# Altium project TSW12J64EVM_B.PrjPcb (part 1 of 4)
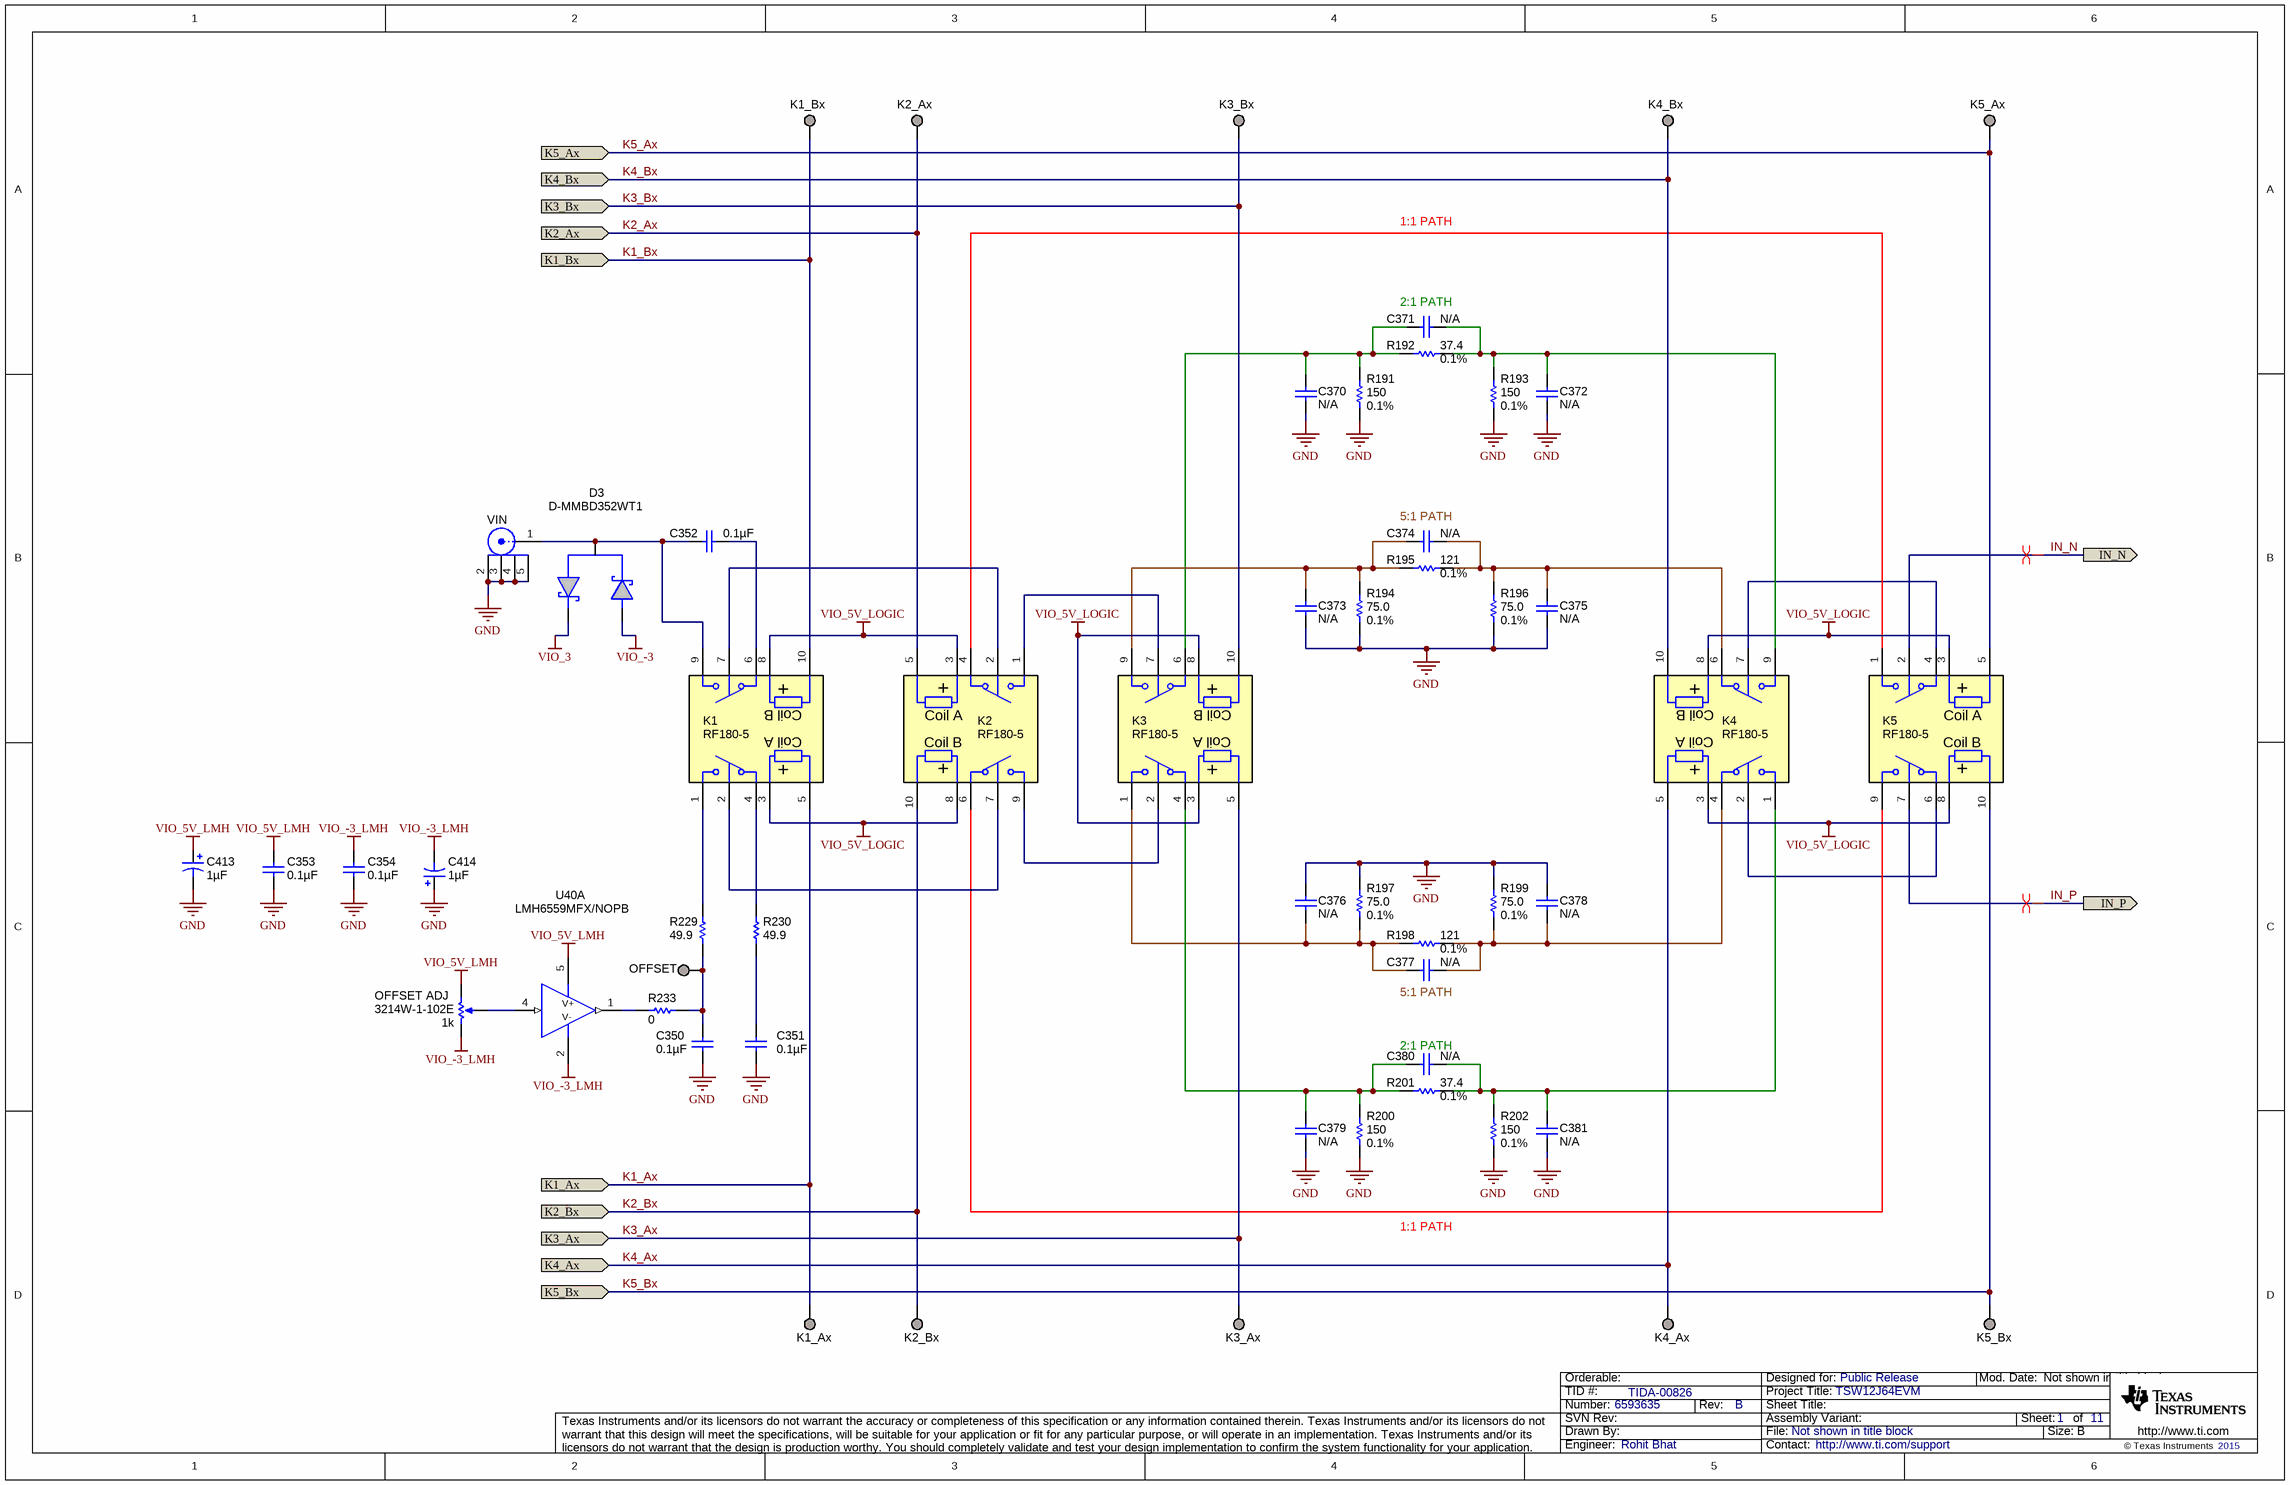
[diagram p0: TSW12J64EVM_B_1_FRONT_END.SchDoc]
TID: TIDA-00826; TechSupport: http://www.ti.com/support; SCH_Rev: B; PRJ_Title: TSW12J64EVM; PRJ_Number: 6593635; PRJ_Engineer: Rohit Bhat; PRJ_Customer: Public Release; PCB_Rev: B; PCB_Layout: Bob Holtz; CopyrightYear: 2015
10 sheets, 892 parts. Net scope: flat (ports and power ports of the same name join across sheets).
Board file: TSW12J64EVM_B.PcbDoc
Sheets:
  TSW12J64EVM_B_1_FRONT_END.SchDoc
  TSW12J64EVM_B_2_RELAY_CONTROL.SchDoc
  TSW12J64EVM_B_3_ANALOG_IN.SchDoc
  TSW12J64EVM_B_4_ADC_IO.SchDoc
  TSW12J64EVM_B_5_FMC.SchDoc
  TSW12J64EVM_B_6_TRF3765.SchDoc
  TSW12J64EVM_B_8_Power.SchDoc
  TSW12J64EVM_B_9_Power.SchDoc
  TSW12J64EVM_B_10_InterfaceControl.SchDoc
  TSW12J64EVM_B_11_Hardware.SchDoc

## Sheet TSW12J64EVM_B_1_FRONT_END.SchDoc
size 431 x 279 mm; Date: Not shown in title block; ApprovedBy: Not shown in title block; CheckedBy: Not shown in title block; Author: Not shown in title block; CompanyName: Not shown in title block; Engineer: Not shown in title block; Organization: Not shown in title block; Address1: Not shown in title block; Address2: Not shown in title block; Address3: Not shown in title block; Address4: Not shown in title block; DocumentNumber: 1; Revision: Use project parameter SCH_Rev; SheetNumber: 1; SheetTotal: 11; PageSetup: Record=PageOptions¦CenterHorizontal=True¦CenterVertical=True¦PrintScale=1.00¦XCorrection=1.00¦YCorrection=1.00¦PrintKind=0¦BorderSize=5000000¦LeftOffset=0¦BottomOffset=0¦Orientation=2¦PaperLength=1000¦PaperWidth=1000¦Scale=100¦PaperSource=15¦PrintQuality=600¦MediaType=1¦DitherType=10¦PaperKind=Letter¦PrintScaleMode=1

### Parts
C350  ValueDisplayed: 0.1µF  [0402L]  (hidden comment: C1005X5R1A104K)
C351  ValueDisplayed: 0.1µF  [0402L]  (hidden comment: C1005X5R1A104K)
C352  ValueDisplayed: 0.1µF  [0402L]  (hidden comment: C1005X5R1A104K)
C353  ValueDisplayed: 0.1µF  [0402L]  (hidden comment: C1005X5R1A104K)
C354  ValueDisplayed: 0.1µF  [0402L]  (hidden comment: C1005X5R1A104K)
C370  Used in BOM report  [0402L]  (value not drawn)
C371  Used in BOM report  [0402L]  (value not drawn)
C372  Used in BOM report  [0402L]  (value not drawn)
C373  Used in BOM report  [0402L]  (value not drawn)
C374  Used in BOM report  [0402L]  (value not drawn)
C375  Used in BOM report  [0402L]  (value not drawn)
C376  Used in BOM report  [0402L]  (value not drawn)
C377  Used in BOM report  [0402L]  (value not drawn)
C378  Used in BOM report  [0402L]  (value not drawn)
C379  Used in BOM report  [0402L]  (value not drawn)
C380  Used in BOM report  [0402L]  (value not drawn)
C381  Used in BOM report  [0402L]  (value not drawn)
C413  ValueDisplayed: 1µF  [3216-18]  (hidden comment: 293D105X0016A2TE3)
C414  ValueDisplayed: 1µF  [3216-18]  (hidden comment: 293D105X0016A2TE3)
D3  D-MMBD352WT1  [SOT-23]
K1  RF180-5  [Relay_RF180]
K1_Ax  TESTPOINT  [TP_VIA_060RND040]  (value not drawn)  (no BOM)
K1_Bx  TESTPOINT  [TP_VIA_060RND040]  (value not drawn)  (no BOM)
K2  RF180-5  [Relay_RF180]
K2_Ax  TESTPOINT  [TP_VIA_060RND040]  (value not drawn)  (no BOM)
K2_Bx  TESTPOINT  [TP_VIA_060RND040]  (value not drawn)  (no BOM)
K3  RF180-5  [Relay_RF180]
K3_Ax  TESTPOINT  [TP_VIA_060RND040]  (value not drawn)  (no BOM)
K3_Bx  TESTPOINT  [TP_VIA_060RND040]  (value not drawn)  (no BOM)
K4  RF180-5  [Relay_RF180]
K4_Ax  TESTPOINT  [TP_VIA_060RND040]  (value not drawn)  (no BOM)
K4_Bx  TESTPOINT  [TP_VIA_060RND040]  (value not drawn)  (no BOM)
K5  RF180-5  [Relay_RF180]
K5_Ax  TESTPOINT  [TP_VIA_060RND040]  (value not drawn)  (no BOM)
K5_Bx  TESTPOINT  [TP_VIA_060RND040]  (value not drawn)  (no BOM)
OFFSET  TESTPOINT  [TP_VIA_060RND040]  (value not drawn)  (no BOM)
OFFSET_ADJ  3214W-1-102E  value 1k  [TRIM_3214W]
R191  ValueDisplayed: 150  Value1: 0.1%  [0402L]  (hidden comment: ERA-2AEB151X)
R192  ValueDisplayed: 37.4  Value1: 0.1%  [0402L]  (hidden comment: 1-1879213-6)
R193  ValueDisplayed: 150  Value1: 0.1%  [0402L]  (hidden comment: ERA-2AEB151X)
R194  ValueDisplayed: 75.0  Value1: 0.1%  [0402L]  (hidden comment: ERA-2AEB750X)
R195  ValueDisplayed: 121  Value1: 0.1%  [0402L]  (hidden comment: ERA-2AEB1210X)
R196  ValueDisplayed: 75.0  Value1: 0.1%  [0402L]  (hidden comment: ERA-2AEB750X)
R197  ValueDisplayed: 75.0  Value1: 0.1%  [0402L]  (hidden comment: ERA-2AEB750X)
R198  ValueDisplayed: 121  Value1: 0.1%  [0402L]  (hidden comment: ERA-2AEB1210X)
R199  ValueDisplayed: 75.0  Value1: 0.1%  [0402L]  (hidden comment: ERA-2AEB750X)
R200  ValueDisplayed: 150  Value1: 0.1%  [0402L]  (hidden comment: ERA-2AEB151X)
R201  ValueDisplayed: 37.4  Value1: 0.1%  [0402L]  (hidden comment: 1-1879213-6)
R202  ValueDisplayed: 150  Value1: 0.1%  [0402L]  (hidden comment: ERA-2AEB151X)
R229  value 49.9  [0402L]  (hidden comment: CRCW040249R9FKED)
R230  value 49.9  [0402L]  (hidden comment: CRCW040249R9FKED)
R233  value 0  [0402L]  (hidden comment: ERJ-2GE0R00X)
U40  LMH6559MFX/NOPB  [DBV0005A_N]  (part A of 2)
VIN  142-0701-806  [Johnson_142-0701-80x_NoVias]  (value not drawn)

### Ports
IN_N (out), IN_P (out), K1_Ax (in), K1_Bx (in), K2_Ax (in), K2_Bx (in), K3_Ax (in), K3_Bx (in), K4_Ax (in), K4_Bx (in), K5_Ax (in), K5_Bx (in)

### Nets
GND: C350.2 C351.2 C353.2 C354.2 C370.1 C372.1 C373.1 C375.1 C376.2 C378.2 C379.1 C381.1 C413.2(-) C414.1(+) R191.1 R193.1 R194.1 R196.1 R197.2 R199.2 R200.1 R202.1 VIN.2 VIN.3 VIN.4 VIN.5
VIO_3: D3.2(C)
VIO_5V_LMH: C353.1 C413.1(+) OFFSET_ADJ.1(CCW) U40.5(VCC)
VIO_5V_LOGIC: K1.3 K1.8 K2.3 K2.8 K3.3 K3.8 K4.3 K4.8 K5.3 K5.8
VIO_-3: D3.1(A)
VIO_-3_LMH: C354.1 C414.2(-) OFFSET_ADJ.3(CW) U40.2(VEE)
IN_N: K5.2 ; port IN_N
IN_P: K5.7 ; port IN_P
K1_Ax: K1.5 K1_Ax.1 ; port K1_Ax
K1_Bx: K1.10 K1_Bx.1 ; port K1_Bx
K2_Ax: K2.5 K2_Ax.1 ; port K2_Ax
K2_Bx: K2.10 K2_Bx.1 ; port K2_Bx
K3_Ax: K3.5 K3_Ax.1 ; port K3_Ax
K3_Bx: K3.10 K3_Bx.1 ; port K3_Bx
K4_Ax: K4.5 K4_Ax.1 ; port K4_Ax
K4_Bx: K4.10 K4_Bx.1 ; port K4_Bx
K5_Ax: K5.5 K5_Ax.1 ; port K5_Ax
K5_Bx: K5.10 K5_Bx.1 ; port K5_Bx
NetC350_1: C350.1 OFFSET.1 R229.1 R233.2
NetC351_1: C351.1 R230.1
NetC352_1: C352.1 D3.3(C/A) K1.9 VIN.1
NetC352_2: C352.2 K1.6
NetC370_2: C370.2 C371.2 K3.6 R191.2 R192.1
NetC371_1: C371.1 C372.2 K4.9 R192.2 R193.2
NetC373_2: C373.2 C374.2 K3.9 R194.2 R195.1
NetC374_1: C374.1 C375.2 K4.6 R195.2 R196.2
NetC376_1: C376.1 C377.2 K3.1 R197.1 R198.1
NetC377_1: C377.1 C378.1 K4.4 R198.2 R199.1
NetC379_2: C379.2 C380.2 K3.4 R200.2 R201.1
NetC380_1: C380.1 C381.2 K4.1 R201.2 R202.2
NetK1_1: K1.1 R229.2
NetK1_2: K1.2 K2.7
NetK1_4: K1.4 R230.2
NetK1_7: K1.7 K2.2
NetK2_1: K2.1 K3.7
NetK2_4: K2.4 K5.1
NetK2_6: K2.6 K5.9
NetK2_9: K2.9 K3.2
NetK4_2: K4.2 K5.6
NetK4_7: K4.7 K5.4
NetOFFSET_ADJ_2: OFFSET_ADJ.2(WIPER) U40.4(IN)
NetR233_1: R233.1 U40.1(OUT)

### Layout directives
differential pair: IN_N, IN_P

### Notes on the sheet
- 1:1 PATH
- (near C371) 2:1 PATH
- (near C374) 5:1 PATH
- (near C377) 5:1 PATH
- (near C380) 2:1 PATH

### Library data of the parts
C350-C354 = C1005X5R1A104K: CAP, CERM, 0.1uF, 10V, +/-10%, X5R, 0402; Manufacturer: TDK; Polarized: N; CompType: Capacitor; U/M: EA; Cap_F: 0.0000001; Tolerance_%: 10; ESR_Ohm: 0.0186; Value1: 0.0186 ohm; TaMin_C: -55; TaMax_C: 85; Cap_Case: 0402
C370-C381 = Capacitor: CAP, CERM, xxxF, xxV, [TempCo], xx%, [PackageReference]; Polarized: N; U/M: EA
C413 C414 = 293D105X0016A2TE3: CAP, TA, 1 µF, 16 V, +/- 20%, 9.3 ohm, SMD; Manufacturer: Vishay-Sprague; Polarized: Y; CompType: Capacitor; Value: 1uF; U/M: EA; Cap_F: 0.000001; Tolerance_%: 20; Value1: 9.3 ohm; VDC_V: 16; Value2: 16V; ESR_ohm: 9.3; IRMS_A: 0.09; TaMin_C: -55; TaMax_C: 125; Cap_Case: A; AEC Category: Q200
D3 = D-MMBD352WT1: Diode, Dual Switching, Series, 10-mA, 7V; Manufacturer: Diodes; Area: 30600
K1-K5 = RF180-5: Relay, DPDT (2 Form C), , 5 VDC, TH, K1 - K5 Body to be mounted approxiamtely 0.025 inches above PC board but cannot be in contact with the PC board; Manufacturer: Any; SymbolCreator: Altium; Coil Power: 290mW; Coil Resistance: 61 ohms; Coil Voltage: 5 VDC; Time Operate (s): 0.002
K1_Ax K1_Bx K2_Ax K2_Bx K3_Ax K3_Bx K4_Ax K4_Bx K5_Ax K5_Bx OFFSET = TESTPOINT: TEST POINT.  No entry in BOM.
OFFSET_ADJ = 3214W-1-102E: Trimmer, 1k, 0.25W, SMT; Manufacturer: Bourns; Sim Note: Enter the Resistance value and the set point into parameter fields.; SymbolCreator: a0412235
R191 R193 R200 R202 = CRCW0402150RFKED: RES, 150, 0.1%, 0.063 W, 0402; Manufacturer: Panasonic; CompType: Resistor; Value: 150; Value_Code: 150R; Tolerance_%: 1; Power_W: 0.063; Value2: 0.063W; VDC_V: 50; TempCo: 25 ppm/C; U/M: EA
R192 R201 = CRCW040237R4FKED: RES, 37.4, 0.1%, 0.063 W, 0402; Manufacturer: TE Connectivity AMP Connectors; CompType: Resistor; Value: 37.4; Value_Code: 37R4; Tolerance_%: 0.1; Power_W: 0.063; Value2: 0.063W; VDC_V: 50; TempCo: 25 ppm/C; U/M: EA
R194 R196 R197 R199 = CRCW040275R0FKED: RES, 75.0, 0.1%, 0.063 W, 0402; Manufacturer: Panasonic; CompType: Resistor; Value: 75.0; Res_ohm: 75; Value_Code: 75R0; Tolerance_%: 0.1; Power_W: 0.063; Value2: 0.063W; VDC_V: 50; TempCo: 25 ppm/C; U/M: EA
R195 R198 = CRCW0402121RFKED: RES, 121, 0.1%, 0.063 W, 0402; Manufacturer: Panasonic; CompType: Resistor; Value: 121; Value_Code: 121R; Tolerance_%: 0.1; Power_W: 0.063; Value2: 0.063W; VDC_V: 50; TempCo: 25 ppm/C; U/M: EA
R229 R230 = CRCW040249R9FKED: RES, 49.9 ohm, 1%, 0.063W, 0402; Manufacturer: Vishay-Dale; CompType: Resistor; Value_Code: 49R9; Tolerance_%: 1; Power_W: 0.063; VDC_V: 50; TempCo: 100 ppm/C; EIA_Code: E96; U/M: EA
R233 = ERJ-2GE0R00X: RES, 0 ohm, 5%, 0.063W, 0402; Manufacturer: Panasonic; CompType: Resistor; Value_Code: 0000; Tolerance_%: 5; Power_W: 0.063; VDC_V: 50; TempCo: 600 ppm/C; EIA_Code: E24; U/M: EA
U40 = LMH6559MFX/NOPB: High-Speed, Closed-Loop Buffer, DBV0005A; Alternate PartNumber: LMH6559MF/NOPB; Manufacturer: Texas Instruments; SymbolCreator: a0411947; CompType: IC; U/M: EA
VIN = 142-0701-806: Connector, SMT, End launch SMA 50 ohm; Manufacturer: Emerson Network Power; Value: 50 Ohm; U/M: EA

## Sheet TSW12J64EVM_B_2_RELAY_CONTROL.SchDoc
size 431 x 279 mm; Date: Not shown in title block; ApprovedBy: Not shown in title block; CheckedBy: Not shown in title block; Author: Not shown in title block; CompanyName: Not shown in title block; Engineer: Not shown in title block; Organization: Not shown in title block; Address1: Not shown in title block; Address2: Not shown in title block; Address3: Not shown in title block; Address4: Not shown in title block; DocumentNumber: 2; Revision: Use project parameter SCH_Rev; SheetNumber: 2; SheetTotal: 11; PageSetup: Record=PageOptions¦CenterHorizontal=True¦CenterVertical=True¦PrintScale=1.00¦XCorrection=1.00¦YCorrection=1.00¦PrintKind=0¦BorderSize=5000000¦LeftOffset=0¦BottomOffset=0¦Orientation=2¦PaperLength=1000¦PaperWidth=1000¦Scale=100¦PaperSource=15¦PrintQuality=600¦MediaType=1¦DitherType=10¦PaperKind=Letter¦PrintScaleMode=1
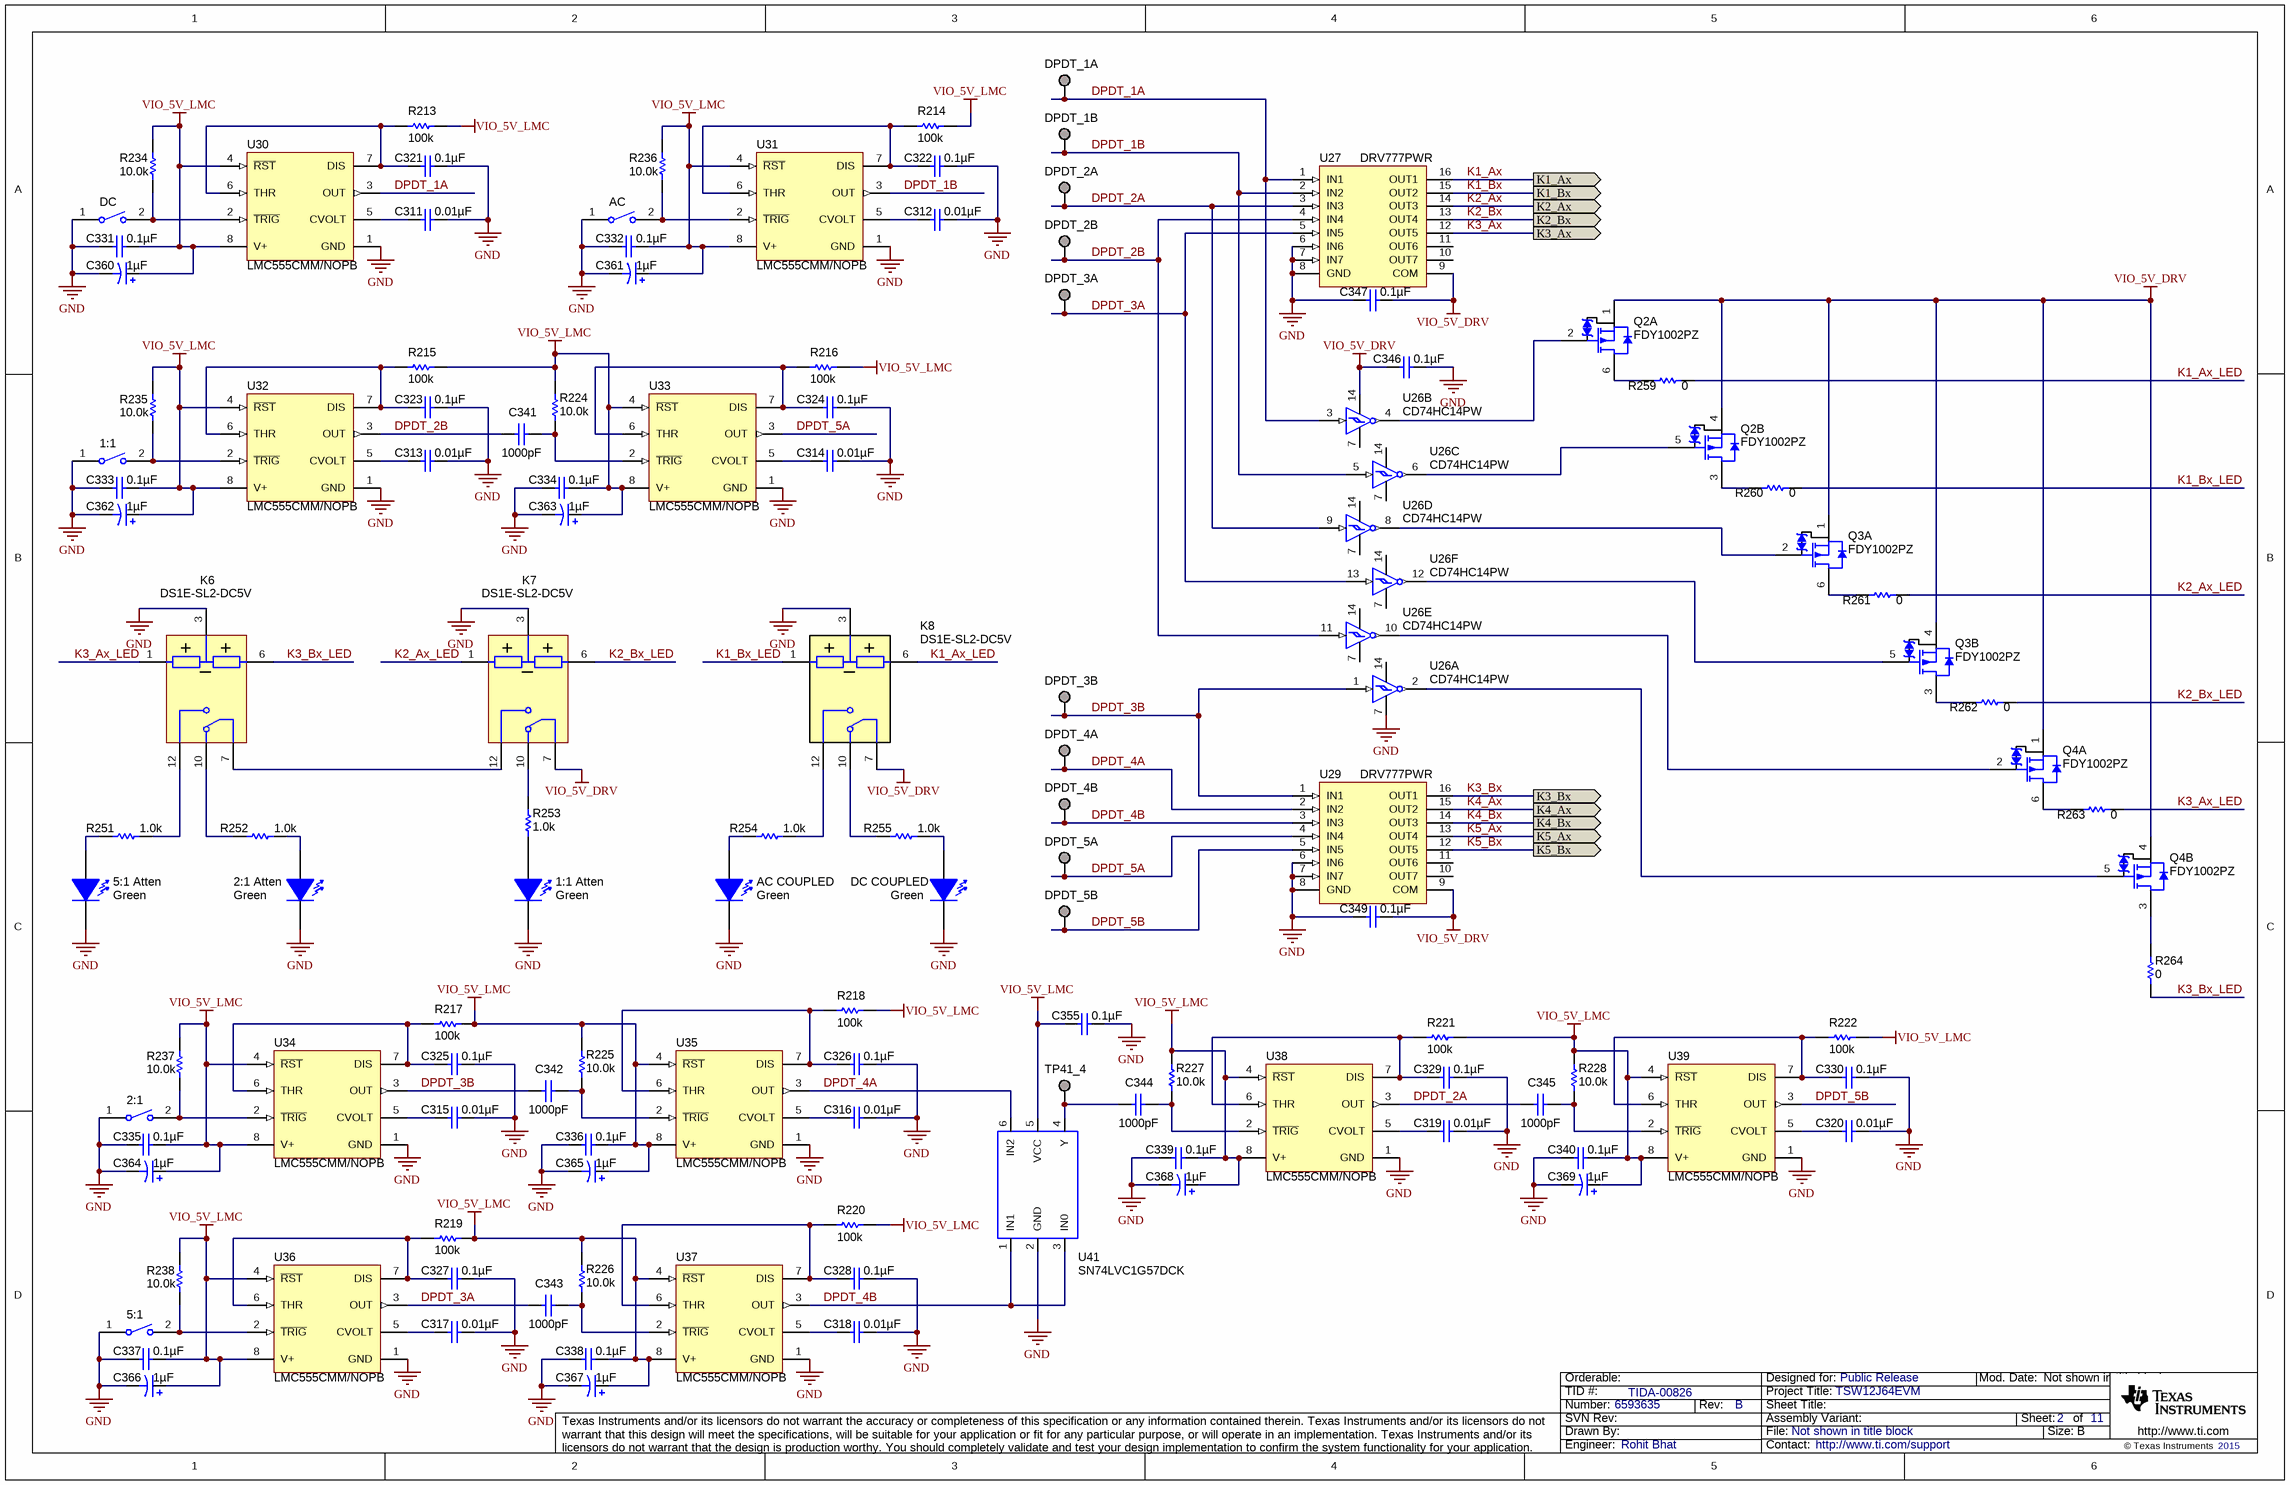
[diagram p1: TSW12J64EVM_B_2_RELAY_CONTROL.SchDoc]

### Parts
1:1  RS-032G05A3-SM RT  [SW_RS-032G05A3-SM]  (value not drawn)
1:1_Atten  value Green  [LED_LTST-C190]  (hidden comment: LTST-C190GKT)
2:1  RS-032G05A3-SM RT  [SW_RS-032G05A3-SM]  (value not drawn)
2:1_Atten  value Green  [LED_LTST-C190]  (hidden comment: LTST-C190GKT)
5:1  RS-032G05A3-SM RT  [SW_RS-032G05A3-SM]  (value not drawn)
5:1_Atten  value Green  [LED_LTST-C190]  (hidden comment: LTST-C190GKT)
AC  RS-032G05A3-SM RT  [SW_RS-032G05A3-SM]  (value not drawn)
AC_COUPLED  value Green  [LED_LTST-C190]  (hidden comment: LTST-C190GKT)
C311  ValueDisplayed: 0.01µF  [0402L]  (hidden comment: C1005X7R1C103K)
C312  ValueDisplayed: 0.01µF  [0402L]  (hidden comment: C1005X7R1C103K)
C313  ValueDisplayed: 0.01µF  [0402L]  (hidden comment: C1005X7R1C103K)
C314  ValueDisplayed: 0.01µF  [0402L]  (hidden comment: C1005X7R1C103K)
C315  ValueDisplayed: 0.01µF  [0402L]  (hidden comment: C1005X7R1C103K)
C316  ValueDisplayed: 0.01µF  [0402L]  (hidden comment: C1005X7R1C103K)
C317  ValueDisplayed: 0.01µF  [0402L]  (hidden comment: C1005X7R1C103K)
C318  ValueDisplayed: 0.01µF  [0402L]  (hidden comment: C1005X7R1C103K)
C319  ValueDisplayed: 0.01µF  [0402L]  (hidden comment: C1005X7R1C103K)
C320  ValueDisplayed: 0.01µF  [0402L]  (hidden comment: C1005X7R1C103K)
C321  ValueDisplayed: 0.1µF  [0402L]  (hidden comment: C1005X5R1A104K)
C322  ValueDisplayed: 0.1µF  [0402L]  (hidden comment: C1005X5R1A104K)
C323  ValueDisplayed: 0.1µF  [0402L]  (hidden comment: C1005X5R1A104K)
C324  ValueDisplayed: 0.1µF  [0402L]  (hidden comment: C1005X5R1A104K)
C325  ValueDisplayed: 0.1µF  [0402L]  (hidden comment: C1005X5R1A104K)
C326  ValueDisplayed: 0.1µF  [0402L]  (hidden comment: C1005X5R1A104K)
C327  ValueDisplayed: 0.1µF  [0402L]  (hidden comment: C1005X5R1A104K)
C328  ValueDisplayed: 0.1µF  [0402L]  (hidden comment: C1005X5R1A104K)
C329  ValueDisplayed: 0.1µF  [0402L]  (hidden comment: C1005X5R1A104K)
C330  ValueDisplayed: 0.1µF  [0402L]  (hidden comment: C1005X5R1A104K)
C331  ValueDisplayed: 0.1µF  [0402L]  (hidden comment: C1005X5R1A104K)
C332  ValueDisplayed: 0.1µF  [0402L]  (hidden comment: C1005X5R1A104K)
C333  ValueDisplayed: 0.1µF  [0402L]  (hidden comment: C1005X5R1A104K)
C334  ValueDisplayed: 0.1µF  [0402L]  (hidden comment: C1005X5R1A104K)
C335  ValueDisplayed: 0.1µF  [0402L]  (hidden comment: C1005X5R1A104K)
C336  ValueDisplayed: 0.1µF  [0402L]  (hidden comment: C1005X5R1A104K)
C337  ValueDisplayed: 0.1µF  [0402L]  (hidden comment: C1005X5R1A104K)
C338  ValueDisplayed: 0.1µF  [0402L]  (hidden comment: C1005X5R1A104K)
C339  ValueDisplayed: 0.1µF  [0402L]  (hidden comment: C1005X5R1A104K)
C340  ValueDisplayed: 0.1µF  [0402L]  (hidden comment: C1005X5R1A104K)
C341  ValueDisplayed: 1000pF  [0402L]  (hidden comment: C1005C0G1E102J)
C342  ValueDisplayed: 1000pF  [0402L]  (hidden comment: C1005C0G1E102J)
C343  ValueDisplayed: 1000pF  [0402L]  (hidden comment: C1005C0G1E102J)
C344  ValueDisplayed: 1000pF  [0402L]  (hidden comment: C1005C0G1E102J)
C345  ValueDisplayed: 1000pF  [0402L]  (hidden comment: C1005C0G1E102J)
C346  ValueDisplayed: 0.1µF  [0402L]  (hidden comment: C1005X5R1A104K)
C347  ValueDisplayed: 0.1µF  [0402L]  (hidden comment: C1005X5R1A104K)
C349  ValueDisplayed: 0.1µF  [0402L]  (hidden comment: C1005X5R1A104K)
C355  ValueDisplayed: 0.1µF  [0402L]  (hidden comment: C1005X5R1A104K)
C360  ValueDisplayed: 1µF  [3216-18]  (hidden comment: 293D105X0016A2TE3)
C361  ValueDisplayed: 1µF  [3216-18]  (hidden comment: 293D105X0016A2TE3)
C362  ValueDisplayed: 1µF  [3216-18]  (hidden comment: 293D105X0016A2TE3)
C363  ValueDisplayed: 1µF  [3216-18]  (hidden comment: 293D105X0016A2TE3)
C364  ValueDisplayed: 1µF  [3216-18]  (hidden comment: 293D105X0016A2TE3)
C365  ValueDisplayed: 1µF  [3216-18]  (hidden comment: 293D105X0016A2TE3)
C366  ValueDisplayed: 1µF  [3216-18]  (hidden comment: 293D105X0016A2TE3)
C367  ValueDisplayed: 1µF  [3216-18]  (hidden comment: 293D105X0016A2TE3)
C368  ValueDisplayed: 1µF  [3216-18]  (hidden comment: 293D105X0016A2TE3)
C369  ValueDisplayed: 1µF  [3216-18]  (hidden comment: 293D105X0016A2TE3)
DC  RS-032G05A3-SM RT  [SW_RS-032G05A3-SM]  (value not drawn)
DC_COUPLED  value Green  [LED_LTST-C190]  (hidden comment: LTST-C190GKT)
DPDT_1A  TESTPOINT  [TP_VIA_060RND040]  (value not drawn)  (no BOM)
DPDT_1B  TESTPOINT  [TP_VIA_060RND040]  (value not drawn)  (no BOM)
DPDT_2A  TESTPOINT  [TP_VIA_060RND040]  (value not drawn)  (no BOM)
DPDT_2B  TESTPOINT  [TP_VIA_060RND040]  (value not drawn)  (no BOM)
DPDT_3A  TESTPOINT  [TP_VIA_060RND040]  (value not drawn)  (no BOM)
DPDT_3B  TESTPOINT  [TP_VIA_060RND040]  (value not drawn)  (no BOM)
DPDT_4A  TESTPOINT  [TP_VIA_060RND040]  (value not drawn)  (no BOM)
DPDT_4B  TESTPOINT  [TP_VIA_060RND040]  (value not drawn)  (no BOM)
DPDT_5A  TESTPOINT  [TP_VIA_060RND040]  (value not drawn)  (no BOM)
DPDT_5B  TESTPOINT  [TP_VIA_060RND040]  (value not drawn)  (no BOM)
K6  DS1E-SL2-DC5V  [RELAY_DS1E-SL2]
K7  DS1E-SL2-DC5V  [RELAY_DS1E-SL2]
K8  DS1E-SL2-DC5V  [RELAY_DS1E-SL2]
Q2  FDY1002PZ  [SOT-563]  (parts A,B of 2)
Q3  FDY1002PZ  [SOT-563]  (parts A,B of 2)
Q4  FDY1002PZ  [SOT-563]  (parts A,B of 2)
R213  ValueDisplayed: 100k  [0402L]  (hidden comment: CRCW0402100KFKED)
R214  ValueDisplayed: 100k  [0402L]  (hidden comment: CRCW0402100KFKED)
R215  ValueDisplayed: 100k  [0402L]  (hidden comment: CRCW0402100KFKED)
R216  ValueDisplayed: 100k  [0402L]  (hidden comment: CRCW0402100KFKED)
R217  ValueDisplayed: 100k  [0402L]  (hidden comment: CRCW0402100KFKED)
R218  ValueDisplayed: 100k  [0402L]  (hidden comment: CRCW0402100KFKED)
R219  ValueDisplayed: 100k  [0402L]  (hidden comment: CRCW0402100KFKED)
R220  ValueDisplayed: 100k  [0402L]  (hidden comment: CRCW0402100KFKED)
R221  ValueDisplayed: 100k  [0402L]  (hidden comment: CRCW0402100KFKED)
R222  ValueDisplayed: 100k  [0402L]  (hidden comment: CRCW0402100KFKED)
R224  ValueDisplayed: 10.0k  [0402L]  (hidden comment: CRCW040210K0FKED)
R225  ValueDisplayed: 10.0k  [0402L]  (hidden comment: CRCW040210K0FKED)
R226  ValueDisplayed: 10.0k  [0402L]  (hidden comment: CRCW040210K0FKED)
R227  ValueDisplayed: 10.0k  [0402L]  (hidden comment: CRCW040210K0FKED)
R228  ValueDisplayed: 10.0k  [0402L]  (hidden comment: CRCW040210K0FKED)
R234  value 10.0k  [0402L]  (hidden comment: CRCW040210K0FKED)
R235  value 10.0k  [0402L]  (hidden comment: CRCW040210K0FKED)
R236  value 10.0k  [0402L]  (hidden comment: CRCW040210K0FKED)
R237  value 10.0k  [0402L]  (hidden comment: CRCW040210K0FKED)
R238  value 10.0k  [0402L]  (hidden comment: CRCW040210K0FKED)
R251  value 1.0k  [1206L]  (hidden comment: CRCW12061K00JNEA)
R252  value 1.0k  [1206L]  (hidden comment: CRCW12061K00JNEA)
R253  value 1.0k  [1206L]  (hidden comment: CRCW12061K00JNEA)
R254  value 1.0k  [1206L]  (hidden comment: CRCW12061K00JNEA)
R255  value 1.0k  [1206L]  (hidden comment: CRCW12061K00JNEA)
R259  value 0  [0603L]  (hidden comment: ERJ-3GEY0R00V)
R260  value 0  [0603L]  (hidden comment: ERJ-3GEY0R00V)
R261  value 0  [0603L]  (hidden comment: ERJ-3GEY0R00V)
R262  value 0  [0603L]  (hidden comment: ERJ-3GEY0R00V)
R263  value 0  [0603L]  (hidden comment: ERJ-3GEY0R00V)
R264  value 0  [0603L]  (hidden comment: ERJ-3GEY0R00V)
TP41_4  TESTPOINT  [TP_VIA_060RND040]  (value not drawn)  (no BOM)
U26  CD74HC14PW  [PW0014A_N]  (parts A,B,C,D,E,F of 6)
U27  DRV777PWR  [PW0016A_N]
U29  DRV777PWR  [PW0016A_N]
U30  LMC555CMM/NOPB  [MUA08A_N]
U31  LMC555CMM/NOPB  [MUA08A_N]
U32  LMC555CMM/NOPB  [MUA08A_N]
U33  LMC555CMM/NOPB  [MUA08A_N]
U34  LMC555CMM/NOPB  [MUA08A_N]
U35  LMC555CMM/NOPB  [MUA08A_N]
U36  LMC555CMM/NOPB  [MUA08A_N]
U37  LMC555CMM/NOPB  [MUA08A_N]
U38  LMC555CMM/NOPB  [MUA08A_N]
U39  LMC555CMM/NOPB  [MUA08A_N]
U41  SN74LVC1G57DCK  [DCK-6]

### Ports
K1_Ax (out), K1_Bx (out), K2_Ax (out), K2_Bx (out), K3_Ax (out), K3_Bx (out), K4_Ax (out), K4_Bx (out), K5_Ax (out), K5_Bx (out)

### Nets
GND: 1:1.1 1:1_Atten.2(K) 2:1.1 2:1_Atten.2(K) 5:1.1 5:1_Atten.2(K) AC.1 AC_COUPLED.2(K) C311.2 C312.2 C313.2 C314.2 C315.2 C316.2 C317.2 C318.2 C319.2 C320.2 C321.2 C322.2 C323.2 C324.2 C325.2 C326.2 C327.2 C328.2 C329.2 C330.2 C331.1 C332.1 C333.1 C334.1 C335.1 C336.1 C337.1 C338.1 C339.1 C340.1 C346.2 C347.1 C349.1 C355.2 C360.2(-) C361.2(-) C362.2(-) C363.2(-) C364.2(-) C365.2(-) C366.2(-) C367.2(-) C368.2(-) C369.2(-) DC.1 DC_COUPLED.2(K) K6.3 K7.3 K8.3 U26.7(GND) U27.6(IN6) U27.7(IN7) U27.8(GND) U29.6(IN6) U29.7(IN7) U29.8(GND) U30.1(GND) U31.1(GND) U32.1(GND) U33.1(GND) U34.1(GND) U35.1(GND) U36.1(GND) U37.1(GND) U38.1(GND) U39.1(GND) U41.2(GND)
VIO_5V_DRV: C346.1 C347.2 C349.2 K7.7 K8.7 Q2.1(S) Q2.4(S) Q3.1(S) Q3.4(S) Q4.1(S) Q4.4(S) U26.14(VCC) U27.9(COM) U29.9(COM)
VIO_5V_LMC: C331.2 C332.2 C333.2 C334.2 C335.2 C336.2 C337.2 C338.2 C339.2 C340.2 C355.1 C360.1(+) C361.1(+) C362.1(+) C363.1(+) C364.1(+) C365.1(+) C366.1(+) C367.1(+) C368.1(+) C369.1(+) R213.1 R214.1 R215.1 R216.1 R217.1 R218.1 R219.1 R220.1 R221.1 R222.1 R224.2 R225.2 R226.2 R227.2 R228.2 R234.2 R235.2 R236.2 R237.2 R238.2 U30.4(~{RST}) U30.8(V+) U31.4(~{RST}) U31.8(V+) U32.4(~{RST}) U32.8(V+) U33.4(~{RST}) U33.8(V+) U34.4(~{RST}) U34.8(V+) U35.4(~{RST}) U35.8(V+) U36.4(~{RST}) U36.8(V+) U37.4(~{RST}) U37.8(V+) U38.4(~{RST}) U38.8(V+) U39.4(~{RST}) U39.8(V+) U41.5(VCC)
DPDT_1A: DPDT_1A.1 U26.3(2A) U27.1(IN1) U30.3(OUT)
DPDT_1B: DPDT_1B.1 U26.5(3A) U27.2(IN2) U31.3(OUT)
DPDT_2A: C345.2 DPDT_2A.1 U26.9(4A) U27.3(IN3) U38.3(OUT)
DPDT_2B: C341.2 DPDT_2B.1 U26.11(5A) U27.4(IN4) U32.3(OUT)
DPDT_3A: C343.2 DPDT_3A.1 U26.13(6A) U27.5(IN5) U36.3(OUT)
DPDT_3B: C342.2 DPDT_3B.1 U26.1(1A) U29.1(IN1) U34.3(OUT)
DPDT_4A: DPDT_4A.1 U29.2(IN2) U35.3(OUT) U41.6(IN2)
DPDT_4B: DPDT_4B.1 U29.3(IN3) U37.3(OUT) U41.1(IN1) U41.3(IN0)
DPDT_5A: DPDT_5A.1 U29.4(IN4) U33.3(OUT)
DPDT_5B: DPDT_5B.1 U29.5(IN5) U39.3(OUT)
K1_Ax: U27.16(OUT1) ; port K1_Ax
K1_Ax_LED: K8.6 R259.2
K1_Bx: U27.15(OUT2) ; port K1_Bx
K1_Bx_LED: K8.1 R260.2
K2_Ax: U27.14(OUT3) ; port K2_Ax
K2_Ax_LED: K7.1 R261.2
K2_Bx: U27.13(OUT4) ; port K2_Bx
K2_Bx_LED: K7.6 R262.2
K3_Ax: U27.12(OUT5) ; port K3_Ax
K3_Ax_LED: K6.1 R263.2
K3_Bx: U29.16(OUT1) ; port K3_Bx
K3_Bx_LED: K6.6 R264.2
K4_Ax: U29.15(OUT2) ; port K4_Ax
K4_Bx: U29.14(OUT3) ; port K4_Bx
K5_Ax: U29.13(OUT4) ; port K5_Ax
K5_Bx: U29.12(OUT5) ; port K5_Bx
Net1:1_2: 1:1.2 R235.1 U32.2(~{TRIG})
Net1:1_Atten_1: 1:1_Atten.1(A) R253.2
Net2:1_2: 2:1.2 R237.1 U34.2(~{TRIG})
Net2:1_Atten_1: 2:1_Atten.1(A) R252.1
Net5:1_2: 5:1.2 R238.1 U36.2(~{TRIG})
Net5:1_Atten_1: 5:1_Atten.1(A) R251.2
NetAC_2: AC.2 R236.1 U31.2(~{TRIG})
NetAC_COUPLED_1: AC_COUPLED.1(A) R254.2
NetC311_1: C311.1 U30.5(CVOLT)
NetC312_1: C312.1 U31.5(CVOLT)
NetC313_1: C313.1 U32.5(CVOLT)
NetC314_1: C314.1 U33.5(CVOLT)
NetC315_1: C315.1 U34.5(CVOLT)
NetC316_1: C316.1 U35.5(CVOLT)
NetC317_1: C317.1 U36.5(CVOLT)
NetC318_1: C318.1 U37.5(CVOLT)
NetC319_1: C319.1 U38.5(CVOLT)
NetC320_1: C320.1 U39.5(CVOLT)
NetC321_1: C321.1 R213.2 U30.6(THR) U30.7(DIS)
NetC322_1: C322.1 R214.2 U31.6(THR) U31.7(DIS)
NetC323_1: C323.1 R215.2 U32.6(THR) U32.7(DIS)
NetC324_1: C324.1 R216.2 U33.6(THR) U33.7(DIS)
NetC325_1: C325.1 R217.2 U34.6(THR) U34.7(DIS)
NetC326_1: C326.1 R218.2 U35.6(THR) U35.7(DIS)
NetC327_1: C327.1 R219.2 U36.6(THR) U36.7(DIS)
NetC328_1: C328.1 R220.2 U37.6(THR) U37.7(DIS)
NetC329_1: C329.1 R221.2 U38.6(THR) U38.7(DIS)
NetC330_1: C330.1 R222.2 U39.6(THR) U39.7(DIS)
NetC341_1: C341.1 R224.1 U33.2(~{TRIG})
NetC342_1: C342.1 R225.1 U35.2(~{TRIG})
NetC343_1: C343.1 R226.1 U37.2(~{TRIG})
NetC344_1: C344.1 R227.1 U38.2(~{TRIG})
NetC344_2: C344.2 TP41_4.1 U41.4(Y)
NetC345_1: C345.1 R228.1 U39.2(~{TRIG})
NetDC_2: DC.2 R234.1 U30.2(~{TRIG})
NetDC_COUPLED_1: DC_COUPLED.1(A) R255.1
NetK6_7: K6.7 K7.12
NetK6_10: K6.10 R252.2
NetK6_12: K6.12 R251.1
NetK7_10: K7.10 R253.1
NetK8_10: K8.10 R255.2
NetK8_12: K8.12 R254.1
NetQ2_2: Q2.2(G) U26.4(2Y)
NetQ2_3: Q2.3(D) R260.1
NetQ2_5: Q2.5(G) U26.6(3Y)
NetQ2_6: Q2.6(D) R259.1
NetQ3_2: Q3.2(G) U26.8(4Y)
NetQ3_3: Q3.3(D) R262.1
NetQ3_5: Q3.5(G) U26.12(6Y)
NetQ3_6: Q3.6(D) R261.1
NetQ4_2: Q4.2(G) U26.10(5Y)
NetQ4_3: Q4.3(D) R264.1
NetQ4_5: Q4.5(G) U26.2(1Y)
NetQ4_6: Q4.6(D) R263.1

Not connected (* = marked no-connect by the designer): U27 10(OUT7) 11(OUT6); U29 10(OUT7) 11(OUT6)

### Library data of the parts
1:1 2:1 5:1 AC DC = RS-032G05A3-SM RT: Switch, Tactile, SPST-NO, 0.05A, 12V, SMD; Manufacturer: C&K Components; SymbolCreator: a0799628; VDC_V: 12; SwitchFunction: Off-Mom; PositionCount: 1; CurrentRating_mA: 50
1:1_Atten 2:1_Atten 5:1_Atten AC_COUPLED DC_COUPLED = LTST-C190GKT: LED, Green, SMD; Manufacturer: Lite-On; Vf_V: 2.1; Value2: 2.1V; Io_A: 0.02; Power_TotalModule: 0.1; Value1: 0.1W; U/M: EA
C311-C320 = C1005X7R1C103K: CAP, CERM, 0.01uF, 16V, +/-10%, X7R, 0402; Manufacturer: TDK; Polarized: N; CompType: Capacitor; U/M: EA; Cap_F: 0.00000001; Tolerance_%: 10; ESR_Ohm: 0.0623; Value1: 0.0623 ohm; VDC_V: 16; TaMin_C: -55; TaMax_C: 125; Cap_Case: 0402
C321-C340 C346 C347 C349 C355 = C1005X5R1A104K: as C350 on sheet TSW12J64EVM_B_1_FRONT_END
C341-C345 = C1005C0G1E102J: CAP, CERM, 1000 pF, 25 V, +/- 5%, C0G/NP0, 0402; Manufacturer: TDK; Polarized: N; CompType: Capacitor; Value: 1000pF; U/M: EA; Cap_F: 0.000000001; Tolerance_%: 5; Value1: Unknown; VDC_V: 25; Value2: 25V; TaMin_C: -55; TaMax_C: 125; Cap_Case: 0402; AEC Category: Q200
C360-C369 = 293D105X0016A2TE3: as C413 on sheet TSW12J64EVM_B_1_FRONT_END
DPDT_1A DPDT_1B DPDT_2A DPDT_2B DPDT_3A DPDT_3B DPDT_4A DPDT_4B DPDT_5A DPDT_5B TP41_4 = TESTPOINT: TEST POINT.  No entry in BOM.
K6 K7 = DS1E-SL2-DC5V: Relay, SPDT (1 Form C), 2A, 5 VDC, TH; Manufacturer: Panasonic; SymbolCreator: Altium; Coil Type: Latching; Coil Voltage: 5 VDC
K8 = DS1E-SL2-DC5V: Relay, SPDT (1 Form C), 2 A, 5 VDC, TH; Manufacturer: Panasonic; SymbolCreator: Altium; Coil Current: 36 mA; Coil Power: 180 mW; Coil Resistance: 139 ohms; Coil Type: Latching; Coil Voltage: 5 VDC; Contact Rating: 2 A; Turn On Voltage (Max): 4 VDC; Time Operate (s): 0.01; Time Release (s): 0.005
Q2-Q4 = FDY1002PZ: MOSFET, P-CH, 20 V, 0.83 A, SOT-563; Manufacturer: Fairchild Semiconductor; Alternate Manufacturer: None; U/M: EA; ChType: P; Value: 20V; VdsMax_V: 20; Value1: 0.83 ohm; Rdson45_ohm: 0.83; Value2: 3.1 nC; QgTyp_nC: 3.1; Vgs_V: 8; AEC Category: Q101
R213-R222 = CRCW0402100KFKED: RES, 100 k, 1%, 0.063 W, 0402; Manufacturer: Vishay-Dale; CompType: Resistor; Value: 100k; Res_ohm: 100000; Tolerance_%: 1; Power_W: 0.063; Value2: 0.063W; VDC_V: 50; TempCo: 100 ppm/C; EIA_Code: E96; U/M: EA
R224-R228 = CRCW040210K0FKED: RES, 10.0 k, 1%, 0.063 W, 0402; Manufacturer: Vishay-Dale; CompType: Resistor; Value: 10.0k; Res_ohm: 10000; Value_Code: 10k0; Tolerance_%: 1; Power_W: 0.063; Value2: 0.063W; VDC_V: 50; TempCo: 100 ppm/C; EIA_Code: E96; U/M: EA; AEC Category: Q200
R234-R238 = CRCW040210K0FKED: RES, 10.0k ohm, 1%, 0.063W, 0402; Manufacturer: Vishay-Dale; CompType: Resistor; Res_ohm: 10000; Value_Code: 10k0; Tolerance_%: 1; Power_W: 0.063; VDC_V: 50; TempCo: 100 ppm/C; EIA_Code: E96; U/M: EA
R251-R255 = CRCW12061K00JNEA: RES, 1.0k ohm, 5%, 0.25W, 1206; Manufacturer: Vishay-Dale; CompType: Resistor; Res_ohm: 1000; Value_Code: 1k00; Tolerance_%: 5; Power_W: 0.25; VDC_V: 200; TempCo: 200 ppm/C; EIA_Code: E24; U/M: EA
R259-R264 = ERJ-3GEY0R00V: RES, 0 ohm, 5%, 0.1W, 0603; Manufacturer: Panasonic; CompType: Resistor; Value_Code: 0000; Tolerance_%: 5; Power_W: 0.1; VDC_V: 50; TempCo: 600 ppm/C; EIA_Code: E24; U/M: EA
U26 = CD74HC14PW: High-Speed CMOS Logic Hex Inverting Schmitt Triggers, PW0014A; Manufacturer: Texas Instruments; SymbolCreator: a0411947; CompType: IC; U/M: EA
U27 U29 = DRV777PWR: 7- bit Integrated Motor and Relay Driver, PW0016A; Manufacturer: Texas Instruments; SymbolCreator: a0411947; CompType: IC; U/M: EA
U30-U39 = LMC555CMM/NOPB: CMOS Timer, 8-pin Mini SOIC, Pb-Free; Manufacturer: Texas Instruments; PackageTopMarking: ZXTT*ZC5; PowerWise: N; CompType: Analog IC
U41 = SN74LVC1G57DCK: IC, Configurable Multiple-Function Gate; Manufacturer: TI; Alternate Manufacturer: None; Area: 19500

## Sheet TSW12J64EVM_B_3_ANALOG_IN.SchDoc
size 431 x 279 mm; Date: Not shown in title block; ApprovedBy: Not shown in title block; CheckedBy: Not shown in title block; Author: Not shown in title block; CompanyName: Not shown in title block; Engineer: Not shown in title block; Organization: Not shown in title block; Address1: Not shown in title block; Address2: Not shown in title block; Address3: Not shown in title block; Address4: Not shown in title block; DocumentNumber: 3; Revision: Use project parameter SCH_Rev; SheetNumber: 3; SheetTotal: 11; PageSetup: Record=PageOptions¦CenterHorizontal=True¦CenterVertical=True¦PrintScale=1.32¦XCorrection=1.00¦YCorrection=1.00¦PrintKind=0¦BorderSize=5000000¦LeftOffset=0¦BottomOffset=0¦Orientation=2¦PaperLength=1000¦PaperWidth=1000¦Scale=100¦PaperSource=15¦PrintQuality=600¦MediaType=1¦DitherType=10¦PaperKind=Letter¦PrintScaleMode=1
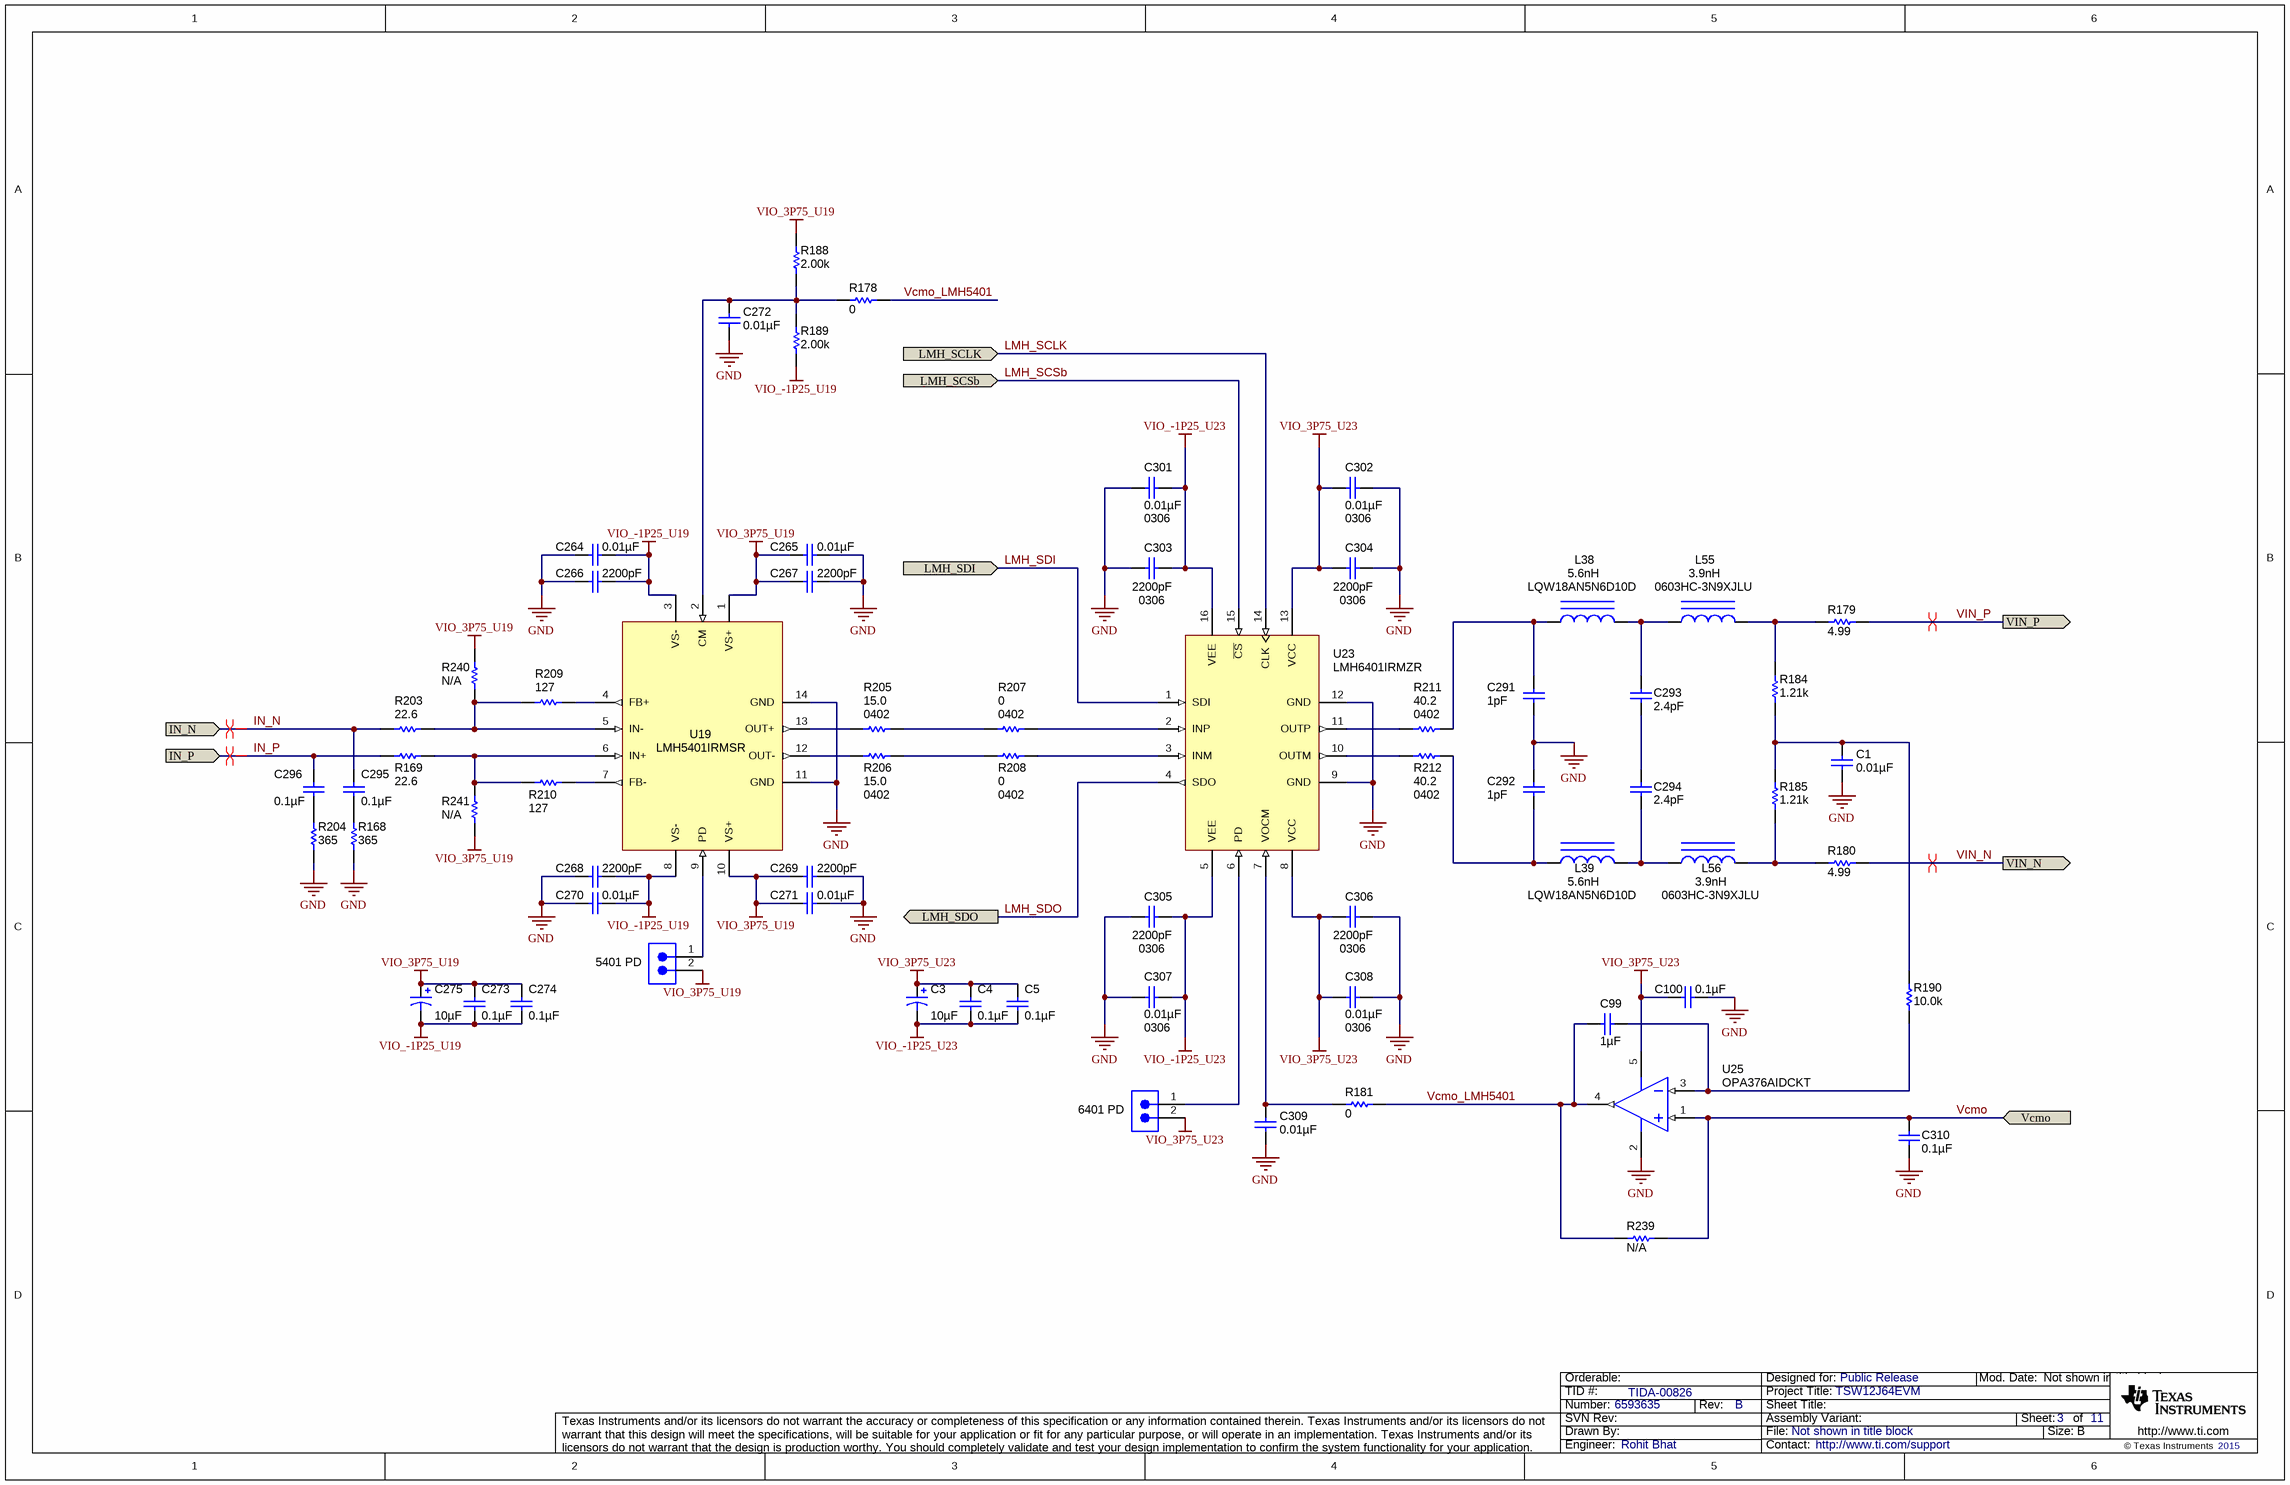
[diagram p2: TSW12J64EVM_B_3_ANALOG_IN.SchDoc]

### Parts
5401_PD  TSW-102-07-G-S  [TSW-102-07-G-S]  (value not drawn)
6401_PD  TSW-102-07-G-S  [TSW-102-07-G-S]  (value not drawn)
C1  ValueDisplayed: 0.01µF  [0402L]  (hidden comment: C1005X7R1E103K)
C3  ValueDisplayed: 10µF  [3216-18]  (hidden comment: TPSA106K010R0900)
C4  ValueDisplayed: 0.1µF  [0402L]  (hidden comment: C1005X5R1A104K)
C5  ValueDisplayed: 0.1µF  [0402L]  (hidden comment: C1005X5R1A104K)
C99  ValueDisplayed: 1µF  [0603L]  (hidden comment: C1608X5R1A105K)
C100  ValueDisplayed: 0.1µF  [0402L]  (hidden comment: C1005X5R1A104K)
C264  ValueDisplayed: 0.01µF  [0306]  (hidden comment: LLL185R71E103MA01L)
C265  ValueDisplayed: 0.01µF  [0306]  (hidden comment: LLL185R71E103MA01L)
C266  ValueDisplayed: 2200pF  [0306]  (hidden comment: LLL185R71H222MA01L)
C267  ValueDisplayed: 2200pF  [0306]  (hidden comment: LLL185R71H222MA01L)
C268  ValueDisplayed: 2200pF  [0306]  (hidden comment: LLL185R71H222MA01L)
C269  ValueDisplayed: 2200pF  [0306]  (hidden comment: LLL185R71H222MA01L)
C270  ValueDisplayed: 0.01µF  [0306]  (hidden comment: LLL185R71E103MA01L)
C271  ValueDisplayed: 0.01µF  [0306]  (hidden comment: LLL185R71E103MA01L)
C272  ValueDisplayed: 0.01µF  [0402L]  (hidden comment: C1005X7R1E103K)
C273  ValueDisplayed: 0.1µF  [0402L]  (hidden comment: C1005X5R1A104K)
C274  ValueDisplayed: 0.1µF  [0402L]  (hidden comment: C1005X5R1A104K)
C275  ValueDisplayed: 10µF  [3216-18]  (hidden comment: TPSA106K010R0900)
C291  ValueDisplayed: 1pF  [0402L]  (hidden comment: GRM1555C1H1R0CA01D)
C292  ValueDisplayed: 1pF  [0402L]  (hidden comment: GRM1555C1H1R0CA01D)
C293  ValueDisplayed: 2.4pF  [0402L]  (hidden comment: GRM1555C1H2R4CA01D)
C294  ValueDisplayed: 2.4pF  [0402L]  (hidden comment: GRM1555C1H2R4CA01D)
C295  ValueDisplayed: 0.1µF  [0402L]  (hidden comment: C1005X5R1A104K)
C296  ValueDisplayed: 0.1µF  [0402L]  (hidden comment: C1005X5R1A104K)
C301  ValueDisplayed: 0.01µF  [0306]  (hidden comment: LLL185R71E103MA01L)
C302  ValueDisplayed: 0.01µF  [0306]  (hidden comment: LLL185R71E103MA01L)
C303  ValueDisplayed: 2200pF  [0306]  (hidden comment: LLL185R71H222MA01L)
C304  ValueDisplayed: 2200pF  [0306]  (hidden comment: LLL185R71H222MA01L)
C305  ValueDisplayed: 2200pF  [0306]  (hidden comment: LLL185R71H222MA01L)
C306  ValueDisplayed: 2200pF  [0306]  (hidden comment: LLL185R71H222MA01L)
C307  ValueDisplayed: 0.01µF  [0306]  (hidden comment: LLL185R71E103MA01L)
C308  ValueDisplayed: 0.01µF  [0306]  (hidden comment: LLL185R71E103MA01L)
C309  ValueDisplayed: 0.01µF  [0402L]  (hidden comment: C1005X7R1E103K)
C310  ValueDisplayed: 0.1µF  [0402L]  (hidden comment: C1005X5R1A104K)
L38  LQW18AN5N6D10D  ValueDisplayed: 5.6nH  [LQW18A]
L39  LQW18AN5N6D10D  ValueDisplayed: 5.6nH  [LQW18A]
L55  0603HC-3N9XJLU  ValueDisplayed: 3.9nH  [0603HC]
L56  0603HC-3N9XJLU  ValueDisplayed: 3.9nH  [0603HC]
R168  ValueDisplayed: 365  [0402L]  (hidden comment: CRCW0402365RFKED)
R169  ValueDisplayed: 22.6  [0402L]  (hidden comment: CRCW040222R6FKED)
R178  value 0  [0402L]  (hidden comment: CRCW04020000Z0ED)
R179  ValueDisplayed: 4.99  [0402L]  (hidden comment: CRCW04024R99FKED)
R180  ValueDisplayed: 4.99  [0402L]  (hidden comment: CRCW04024R99FKED)
R181  value 0  [0402L]  (hidden comment: CRCW04020000Z0ED)
R184  ValueDisplayed: 1.21k  [0402L]  (hidden comment: CRCW04021K21FKED)
R185  ValueDisplayed: 1.21k  [0402L]  (hidden comment: CRCW04021K21FKED)
R188  ValueDisplayed: 2.00k  [0402L]  (hidden comment: CRCW04022K00FKED)
R189  ValueDisplayed: 2.00k  [0402L]  (hidden comment: CRCW04022K00FKED)
R190  value 10.0k  [0402L]  (hidden comment: CRCW040210K0FKED)
R203  ValueDisplayed: 22.6  [0402L]  (hidden comment: CRCW040222R6FKED)
R204  ValueDisplayed: 365  [0402L]  (hidden comment: CRCW0402365RFKED)
R205  ValueDisplayed: 15.0  PackageReference: 0402  [0402L]  (hidden comment: CRCW040215R0FKED)
R206  ValueDisplayed: 15.0  PackageReference: 0402  [0402L]  (hidden comment: CRCW040215R0FKED)
R207  ValueDisplayed: 0  PackageReference: 0402  [0402L]  (hidden comment: CRCW04020000Z0ED)
R208  ValueDisplayed: 0  PackageReference: 0402  [0402L]  (hidden comment: CRCW04020000Z0ED)
R209  ValueDisplayed: 127  [0402L]  (hidden comment: CRCW0402127RFKED)
R210  ValueDisplayed: 127  [0402L]  (hidden comment: CRCW0402127RFKED)
R211  value 40.2  PackageReference: 0402  [0402L]  (hidden comment: CRCW040240R2FKED)
R212  value 40.2  PackageReference: 0402  [0402L]  (hidden comment: CRCW040240R2FKED)
R239  Used in BOM report  [0402L]  (value not drawn)
R240  Used in BOM report  [0402L]  (value not drawn)
R241  Used in BOM report  [0402L]  (value not drawn)
U19  LMH5401IRMSR  [RMS0014A]
U23  LMH6401IRMZR  [RMZ0016A]
U25  OPA376AIDCKT  [DCK0005A_N]

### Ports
IN_N (in), IN_P (in), LMH_SCLK (in), LMH_SCSb (in), LMH_SDI (in), LMH_SDO (out), Vcmo (in), VIN_N (out), VIN_P (out)

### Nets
GND: C1.1 C100.2 C264.1 C265.2 C266.2 C267.1 C268.2 C269.1 C270.1 C271.2 C272.1 C291.2 C292.1 C301.1 C302.2 C303.2 C304.1 C305.2 C306.1 C307.1 C308.2 C309.1 C310.1 R168.1 R204.1 U19.11(GND) U19.14(GND) U23.9(GND) U23.12(GND) U25.2(V-)
VIO_3P75_U19: 5401_PD.2 C265.1 C267.2 C269.2 C271.1 C273.1 C274.1 C275.1(+) R188.2 R240.1 R241.2 U19.1(VS+) U19.10(VS+)
VIO_3P75_U23: 6401_PD.2 C3.1(+) C4.1 C5.1 C100.1 C302.1 C304.2 C306.2 C308.1 U23.8(VCC) U23.13(VCC) U25.5(V+)
VIO_-1P25_U19: C264.2 C266.1 C268.1 C270.2 C273.2 C274.2 C275.2(-) R189.1 U19.3(VS-) U19.8(VS-)
VIO_-1P25_U23: C3.2(-) C4.2 C5.2 C301.2 C303.1 C305.1 C307.2 U23.5(VEE) U23.16(VEE)
IN_N: C295.2 R203.1 ; port IN_N
IN_P: C296.2 R169.2 ; port IN_P
LMH_SCLK: U23.14(CLK) ; port LMH_SCLK
LMH_SCSb: U23.15(~{CS}) ; port LMH_SCSb
LMH_SDI: U23.1(SDI) ; port LMH_SDI
LMH_SDO: U23.4(SDO) ; port LMH_SDO
Vcmo: C310.2 R239.2 U25.1(IN+) ; port Vcmo
Vcmo_LMH5401: C99.1 R178.1 R181.1 R239.1 U25.4(OUT)
VIN_N: R180.2 ; port VIN_N
VIN_P: R179.2 ; port VIN_P
Net5401_PD_1: 5401_PD.1 U19.9(PD)
Net6401_PD_1: 6401_PD.1 U23.6(PD)
NetC1_2: C1.2 R184.2 R185.1 R190.2
NetC99_2: C99.2 R190.1 U25.3(IN-)
NetC272_2: C272.2 R178.2 R188.1 R189.2 U19.2(CM)
NetC291_1: C291.1 L38.1 R211.2
NetC292_2: C292.2 L39.1 R212.2
NetC293_1: C293.1 L38.2 L55.1
NetC293_2: C293.2 C294.1
NetC294_2: C294.2 L39.2 L56.1
NetC295_1: C295.1 R168.2
NetC296_1: C296.1 R204.2
NetC309_2: C309.2 R181.2 U23.7(VOCM)
NetL55_2: L55.2 R179.1 R184.1
NetL56_2: L56.2 R180.1 R185.2
NetR169_1: R169.1 R210.2 R241.1 U19.6(IN+)
NetR203_2: R203.2 R209.2 R240.2 U19.5(IN-)
NetR205_1: R205.1 U19.13(OUT+)
NetR205_2: R205.2 R207.1
NetR206_1: R206.1 U19.12(OUT-)
NetR206_2: R206.2 R208.2
NetR207_2: R207.2 U23.2(INP)
NetR208_1: R208.1 U23.3(INM)
NetR209_1: R209.1 U19.4(FB+)
NetR210_1: R210.1 U19.7(FB-)
NetR211_1: R211.1 U23.11(OUTP)
NetR212_1: R212.1 U23.10(OUTM)

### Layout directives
differential pair: IN_N, IN_P, VIN_N, VIN_P

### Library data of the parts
5401_PD 6401_PD = TSW-102-07-G-S: Header, TH, 100mil, 2x1, Gold plated, 230 mil above insulator; Manufacturer: Samtec, Inc.; U/M: EA
C1 C272 C309 = C1005X7R1E103K: CAP, CERM, 0.01uF, 25V, +/-10%, X7R, 0402; Manufacturer: TDK; Cap_Case: 0402; ESR_Ohm: 0.0623; Polarized: N; TaMax_C: 125; TaMin_C: -55; Tolerance_%: 10; VDC_V: 25; Cap_F: 10.0E-9; CompType: Capacitor; Value1: 0.0623 ohm
C3 C275 = TPSA106K010R0900: CAP, TA, 10uF, 10V, +/-10%, 0.9 ohm, SMD; Manufacturer: AVX; Polarized: Y; CompType: Capacitor; U/M: EA; Cap_F: 0.00001; Tolerance_%: 10; Value1: 0.9 ohm; ESR_Ohm: 0.9; IRMS_A: 0.26; TaMin_C: -55; TaMax_C: 125; Cap_Case: A
C4 C5 C100 C273 C274 C295 C296 C310 = C1005X5R1A104K: as C350 on sheet TSW12J64EVM_B_1_FRONT_END
C99 = C1608X5R1A105K: CAP, CERM, 1uF, 10V, +/-10%, X5R, 0603; Manufacturer: TDK; Polarized: N; CompType: Capacitor; U/M: EA; Cap_F: 0.000001; Tolerance_%: 10; ESR_Ohm: 0.0057; Value1: 0.0057 ohm; TaMin_C: -55; TaMax_C: 85; Cap_Case: 0603
C264 C265 C270 C271 C301 C302 C307 C308 = LLL185R71E103MA01L: CAP, CERM, 0.01uF, 25V, +/-20%, X7R, 0306; Manufacturer: MuRata; Polarized: N; CompType: Capacitor; U/M: EA; Cap_F: 0.00000001; Tolerance_%: 20; Value1: Unknown; VDC_V: 25; TaMin_C: -55; TaMax_C: 125
C266-C269 C303-C306 = LLL185R71H222MA01L: CAP, CERM, 2200pF, 50V, +/-20%, X7R, 0306; Manufacturer: MuRata; Polarized: N; CompType: Capacitor; U/M: EA; Cap_F: 0.0000000022; Tolerance_%: 20; Value1: Unknown; VDC_V: 50; TaMin_C: -55; TaMax_C: 125
C291 C292 = GRM1555C1H1R0CA01D: CAP, CERM, 1 pF, 50 V, +/- 5%, C0G/NP0, 0402; Manufacturer: MuRata; Polarized: N; CompType: Capacitor; Value: 1pF; U/M: EA; Cap_F: 0.000000000001; Tolerance_%: 5; Value1: Unknown; VDC_V: 50; Value2: 50V; TaMin_C: -55; TaMax_C: 125; Cap_Case: 0402
C293 C294 = GRM1555C1H2R4CA01D: CAP, CERM, 2.4 pF, 50 V, +/- 5%, C0G/NP0, 0402; Manufacturer: MuRata; Polarized: N; CompType: Capacitor; Value: 2.4pF; U/M: EA; Cap_F: 0.0000000000024; Tolerance_%: 5; Value1: Unknown; VDC_V: 50; Value2: 50V; TaMin_C: -55; TaMax_C: 125; Cap_Case: 0402; AEC Category: Q200
L38 L39 = LQW18AN5N6D10D: Inductor, Wirewound, 5.6 nH, 0.9 A, 0.045 ohm, SMD; Manufacturer: MuRata; Value: 5.6nH; Ind_H: 5.6E-9; Imax_A: 0.9; Irms: 0.9A @ C rise; DCR_ohm: 0.045; Value2: 0.9A; AEC Category: Q200; AEC Qualified: N
L55 L56 = 0603HC-3N9XJLU: Inductor, Wirewound, Ceramic, 3.9 nH, 2.2 A, 0.054 ohm, SMD; Manufacturer: Coilcraft; Value: 3.9nH; Ind_H: 3.9E-9; Imax_A: 2.2; Irms: 2.4A @ 20C rise; DCR_ohm: 0.054; Value2: 2.2A; AEC Category: Q200
R168 R204 = CRCW0402365RFKED: RES, 365, 1%, 0.063 W, 0402; Manufacturer: Vishay-Dale; CompType: Resistor; Value: 365; Value_Code: 365R; Tolerance_%: 1; Power_W: 0.063; Value2: 0.063W; VDC_V: 50; TempCo: 100 ppm/C; EIA_Code: E96; U/M: EA
R169 R203 = CRCW040222R6FKED: RES, 22.6, 1%, 0.063 W, 0402; Manufacturer: Vishay-Dale; CompType: Resistor; Value: 22.6; Value_Code: 22R6; Tolerance_%: 1; Power_W: 0.063; Value2: 0.063W; VDC_V: 50; TempCo: 100 ppm/C; EIA_Code: E96; U/M: EA
R178 R181 = CRCW04020000Z0ED: RES, 0 ohm, 5%, 0.063W, 0402; Manufacturer: Vishay-Dale; CompType: Resistor; Value_Code: 0000; Tolerance_%: 5; Power_W: 0.063; VDC_V: 50; TempCo: 200 ppm/C; EIA_Code: E24; U/M: EA
R179 R180 = CRCW04024R99FKED: RES, 4.99, 1%, 0.063 W, 0402; Manufacturer: Vishay-Dale; CompType: Resistor; Value: 4.99; Value_Code: 4R99; Tolerance_%: 1; Power_W: 0.063; Value2: 0.063W; VDC_V: 50; TempCo: 100 ppm/C; EIA_Code: E96; U/M: EA
R184 R185 = CRCW04021K21FKED: RES, 1.21 k, 1%, 0.063 W, 0402; Manufacturer: Vishay-Dale; CompType: Resistor; Value: 1.21k; Res_ohm: 1210; Value_Code: 1k21; Tolerance_%: 1; Power_W: 0.063; Value2: 0.063W; VDC_V: 50; TempCo: 100 ppm/C; EIA_Code: E96; U/M: EA; AEC Category: Q200
R188 R189 = CRCW04022K00FKED: RES, 2.00 k, 1%, 0.063 W, 0402; Manufacturer: Vishay-Dale; CompType: Resistor; Value: 2.00k; Res_ohm: 2000; Value_Code: 2k00; Tolerance_%: 1; Power_W: 0.063; Value2: 0.063W; VDC_V: 50; TempCo: 100 ppm/C; EIA_Code: E96; U/M: EA
R190 = CRCW040210K0FKED: as R234 on sheet TSW12J64EVM_B_2_RELAY_CONTROL
R205 R206 = CRCW040215R0FKED: RES, 15.0, 1%, 0.063 W, 0402; Manufacturer: Vishay-Dale; CompType: Resistor; Value: 15.0; Res_ohm: 15; Value_Code: 15R0; Tolerance_%: 1; Power_W: 0.063; Value2: 0.063W; VDC_V: 50; TempCo: 100 ppm/C; EIA_Code: E96; U/M: EA; AEC Category: Q200
R207 R208 = CRCW04020000Z0ED: RES, 0, 5%, 0.063 W, 0402; Manufacturer: Vishay-Dale; CompType: Resistor; Value: 0; Value_Code: 0000; Tolerance_%: 5; Power_W: 0.063; Value2: 0.063W; VDC_V: 50; TempCo: 200 ppm/C; EIA_Code: E24; U/M: EA
R209 R210 = CRCW0402127RFKED: RES, 127, 1%, 0.063 W, 0402; Manufacturer: Vishay-Dale; CompType: Resistor; Value: 127; Value_Code: 127R; Tolerance_%: 1; Power_W: 0.063; Value2: 0.063W; VDC_V: 50; TempCo: 100 ppm/C; EIA_Code: E96; U/M: EA
R211 R212 = CRCW040240R2FKED: RES, 40.2 ohm, 1%, 0.063W, 0402; Manufacturer: Vishay-Dale; CompType: Resistor; Value_Code: 40R2; Tolerance_%: 1; Power_W: 0.063; VDC_V: 50; TempCo: 100 ppm/C; EIA_Code: E96; U/M: EA
R239-R241 = Resistor: RES, xxx ohm, x%, xW, [PackageReference]; U/M: EA
U19 = LMH5401RMS: 8GHz Ultra Wideband Fully Differential Amplifier, RMS0014A; Alternate Manufacturer: None; Manufacturer: Texas Instruments; SymbolCreator: Altium; CompType: IC; U/M: EA
U23 = LMH6401IRMZR: 5 GHz Ultra Wideband Digital Variable Gain Amplifier, RMZ0016A; Alternate PartNumber: LMH6401IRMZT; Manufacturer: Texas Instruments; SymbolCreator: Altium; CompType: IC; U/M: EA
U25 = OPA376AIDCKT: Precision, Low Noise, Low Iq Operational Amplifier, 2.2 to 5.5 V, -40 to 125 degC, 5-pin SOT23 (DCK0005A), Green (RoHS & no Sb/Br); Manufacturer: Texas Instruments; Alternate PartNumber: Equivalent; CMRR(Min)(dB): 76; IIB(Max)(pA): 10; Iq per channel(Max)(mA): 0.95; Number of Channels: 1; Offset Drift(Typ)(uV/C): 0.32; Slew Rate(Typ)(V/us): 2; Sub Family: Low Input Bias Current Amp (<=10pA), Low Noise Amp (<=10nV/rtHz), Low Offset Voltage Amplifier (<=500uV), Low Supply Voltage Amplifier (<=2.7V), Precision Amplifier; Total Supply Voltage(Max)(+5V is 5, +/-5V is 10): 5.5; Total Supply Voltage(Min)(+5V is 5, +/-5V is 10): 2.2; Vio (25C)(Max)(mV): 0.025; Vn at 1kHz(Typ)(nV/rtHz): 7.5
